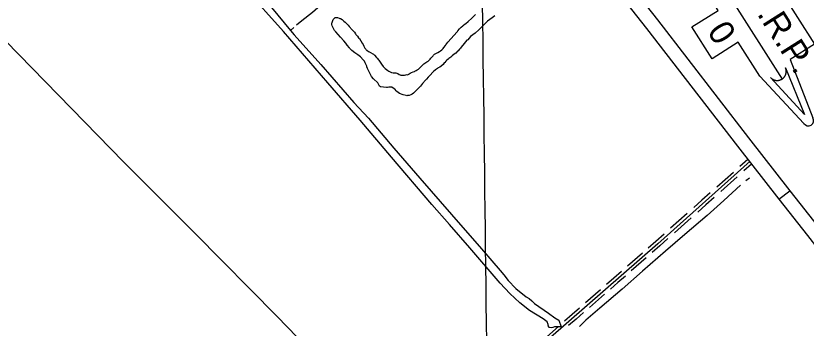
# Model space of a CAD drawing. Extents: x 3702978 to 3741108, y 397120 to 422907.
# Drawn here: x 3712602 to 3716580, y 417744 to 419319 of the extents above; entities that cross this region are included whole.
import ezdxf

# ---------------------------------------------------------------- set-up
doc = ezdxf.new("R2010")
doc.units = 0
for name, color, linetype in [('V-GRID-MAJR', 7, 'Continuous'), ('V-ROAD-CNTR', 7, 'Continuous'), ('V-SITE-VEGE', 7, 'Continuous'), ('V-TOPO-SHOR', 7, 'Continuous'), ('V-TOPO-WATR-IDEN', 7, 'Continuous')]:
    doc.layers.add(name, color=color, linetype=linetype)

msp = doc.modelspace()

# ---------------------------------------------------------------- linework, layer by layer
at = {"layer": 'V-GRID-MAJR'}
msp.add_spline([(3715151.476, 402623.691), (3715079.223, 408681.465), (3715006.939, 414741.843), (3714934.655, 420802.224), (3714934.624, 420804.822)], degree=3, dxfattribs=at)
at = {"layer": 'V-ROAD-CNTR'}
for points in [[(3714437.972, 420803.256), (3714574.337, 420608.545), (3714632.888, 420530.918), (3714682.486, 420466.822), (3714774.706, 420355.931), (3715157.03, 419961.431), (3715290.36, 419827.954), (3715412.039, 419698.216), (3715518.204, 419583.57), (3715775.96, 419254.704), (3716234.559, 418661.29), (3716442.007, 418393.909), (3716585.793, 418210.792), (3716689.926, 418077.31), (3716778.929, 417974.731), (3716867.49, 417879.826), (3716994.236, 417765.208), (3717139.264, 417654.689), (3717417.514, 417482.688), (3717810.191, 417252.227), (3718294.272, 416969.301), (3718986.57, 416565.649), (3719677.821, 416162.816), (3719893.898, 416035.258)], [(3714515.651, 420804.182), (3714630.628, 420650.883), (3714688.859, 420573.679), (3714737.432, 420510.907), (3714827.149, 420403.027), (3715207.239, 420010.832), (3715340.976, 419876.947), (3715463.567, 419746.236), (3715571.853, 419629.301), (3715831.545, 419297.965), (3716290.25, 418704.413), (3716497.531, 418437.247), (3716641.259, 418254.203), (3716744.33, 418122.083), (3716831.295, 418021.854), (3716916.949, 417930.064), (3717039.283, 417819.436), (3717179.223, 417712.794), (3717453.862, 417543.025), (3717845.787, 417313.005), (3718329.782, 417030.13), (3719022.041, 416626.501), (3719713.035, 416223.817), (3719920.188, 416105.369)], [(3716298.122, 418585.3), (3715832.901, 418169.955), (3715201.035, 417616.941), (3714529.227, 417025.75), (3713933.808, 416500.999), (3713913.076, 416483.623)], [(3716286.184, 418594.751), (3716246.594, 418559.406)], [(3716304.618, 418570.99), (3716266.574, 418537.026)], [(3716213.365, 418529.737), (3716130.29, 418455.568)], [(3716233.344, 418507.359), (3716150.27, 418433.19)], [(3716097.06, 418425.901), (3716055.522, 418388.817)], [(3716442.007, 418393.909), (3716497.531, 418437.247)], [(3716055.522, 418388.817), (3716013.984, 418351.733)], [(3716117.04, 418403.521), (3716075.502, 418366.437)], [(3716075.502, 418366.437), (3716033.964, 418329.353)], [(3715980.754, 418322.064), (3715897.679, 418247.895)], [(3716000.734, 418299.686), (3715917.659, 418225.518)], [(3715864.449, 418218.229), (3715822.911, 418181.145)], [(3715823.022, 418181.242), (3715785.411, 418148.324)], [(3715884.429, 418195.849), (3715842.891, 418158.765)], [(3715842.78, 418158.668), (3715805.169, 418125.75)], [(3715755.322, 418121.991), (3715680.1, 418056.156)], [(3715775.08, 418099.415), (3715699.858, 418033.58)], [(3715650.012, 418029.822), (3715612.4, 417996.905)], [(3715612.4, 417996.904), (3715574.789, 417963.986)], [(3715669.77, 418007.246), (3715632.158, 417974.329)], [(3715632.158, 417974.33), (3715594.547, 417941.412)], [(3715544.7, 417937.652), (3715469.478, 417871.817)], [(3715564.458, 417915.078), (3715489.236, 417849.243)], [(3715439.389, 417845.483), (3715401.778, 417812.565)], [(3715459.147, 417822.909), (3715421.536, 417789.991)], [(3715401.778, 417812.566), (3715364.166, 417779.649)], [(3715421.536, 417789.99), (3715383.924, 417757.073)], [(3715334.078, 417753.315), (3715258.855, 417687.481)]]:
    msp.add_lwpolyline(points, dxfattribs=at)
at = {"layer": 'V-SITE-VEGE'}
for points in [[(3714253.027, 419192.391), (3714236.168, 419211.459), (3714212.442, 419237.905), (3714206.197, 419245.288), (3714202.437, 419251.453), (3714194.263, 419268.107), (3714192.353, 419275.523), (3714192.924, 419281.718), (3714194.141, 419284.823), (3714198.359, 419300.33), (3714210.052, 419309.706), (3714215.002, 419310.364), (3714221.815, 419309.794), (3714229.268, 419306.755), (3714232.995, 419304.926), (3714235.477, 419304.324), (3714244.181, 419299.435), (3714253.529, 419291.456), (3714259.75, 419287.17), (3714270.353, 419276.721), (3714274.105, 419271.798), (3714279.722, 419265.647), (3714295.338, 419247.193), (3714305.951, 419235.505), (3714311.577, 419228.118), (3714314.084, 419224.421), (3714320.957, 419215.805), (3714326.585, 419208.416), (3714330.951, 419204.115), (3714338.461, 419193.027), (3714345.365, 419180.696), (3714349.754, 419173.299), (3714353.526, 419165.898), (3714359.168, 419156.032), (3714362.924, 419150.488), (3714366.044, 419147.416), (3714369.152, 419145.581), (3714376.628, 419139.446), (3714381.604, 419136.388), (3714384.084, 419135.788), (3714402.117, 419125.396), (3714406.483, 419121.094), (3714417.104, 419108.173), (3714422.714, 419103.26), (3714426.464, 419098.334), (3714428.96, 419095.876), (3714435.229, 419085.399), (3714442.737, 419074.93), (3714450.868, 419063.846), (3714460.233, 419053.391), (3714473.936, 419042.348), (3714479.531, 419039.292), (3714493.198, 419033.204), (3714501.257, 419032.026), (3714511.165, 419031.479), (3714514.882, 419030.887), (3714519.85, 419029.069), (3714524.198, 419027.244), (3714531.655, 419023.582), (3714536.007, 419021.139), (3714540.349, 419019.933), (3714543.456, 419018.718), (3714551.504, 419018.777), (3714558.922, 419020.072), (3714564.487, 419021.352), (3714567.573, 419022.611), (3714573.15, 419022.036), (3714577.475, 419022.685), (3714580.563, 419023.947), (3714582.402, 419026.437), (3714586.714, 419029.564), (3714594.115, 419033.335), (3714601.527, 419035.866), (3714608.322, 419037.775), (3714610.165, 419039.647), (3714617.573, 419042.796), (3714622.502, 419045.93), (3714628.046, 419049.686), (3714631.126, 419051.566), (3714647.105, 419067.782), (3714656.331, 419075.898), (3714671.112, 419086.536), (3714673.573, 419088.409), (3714676.651, 419090.91), (3714681.577, 419094.662), (3714687.106, 419100.276), (3714690.785, 419105.254), (3714701.836, 419117.72), (3714703.675, 419120.211), (3714706.747, 419123.33), (3714709.211, 419125.206), (3714715.377, 419128.345), (3714726.475, 419134.621), (3714735.105, 419139.636), (3714738.798, 419142.761), (3714746.189, 419147.769), (3714752.335, 419154.007), (3714756.632, 419158.992), (3714763.982, 419169.572), (3714767.054, 419172.689), (3714776.24, 419186.38)], [(3715012.999, 419319.397), (3714998.837, 419308.766), (3714976.677, 419291.268), (3714969.3, 419284.399), (3714941.034, 419255.711), (3714933.034, 419248.84), (3714913.353, 419231.356), (3714901.651, 419223.221), (3714890.575, 419213.854), (3714876.45, 419198.268), (3714872.762, 419195.145), (3714859.259, 419178.947), (3714843.912, 419161.498), (3714839.619, 419155.893), (3714834.708, 419150.286), (3714827.954, 419142.804), (3714824.88, 419139.685), (3714816.282, 419130.334), (3714808.27, 419125.323), (3714798.43, 419116.582), (3714791.661, 419110.96), (3714781.196, 419102.831), (3714778.12, 419100.333), (3714770.126, 419092.843), (3714767.048, 419090.345), (3714760.912, 419082.87), (3714758.447, 419081.612), (3714752.311, 419074.137), (3714743.089, 419065.4), (3714735.695, 419060.393), (3714728.3, 419056.004), (3714723.989, 419052.877), (3714714.748, 419046.616), (3714712.291, 419044.121), (3714705.516, 419039.116), (3714701.825, 419035.995), (3714685.239, 419018.536), (3714677.254, 419009.807), (3714668.664, 418999.217), (3714663.745, 418994.849), (3714648.401, 418976.777), (3714637.973, 418963.699), (3714630.608, 418954.976), (3714622.619, 418946.87), (3714602.938, 418929.386), (3714596.163, 418924.385), (3714589.382, 418920.619), (3714581.974, 418917.467), (3714573.932, 418916.787), (3714570.221, 418916.142), (3714566.498, 418917.352), (3714550.994, 418920.332), (3714533.617, 418926.394), (3714519.918, 418936.817), (3714515.552, 418941.119), (3714510.553, 418947.274), (3714509.297, 418949.739), (3714501.83, 418954.638), (3714494.369, 418958.914), (3714491.269, 418959.514), (3714488.174, 418959.49), (3714478.892, 418958.802), (3714473.328, 418957.522), (3714467.762, 418956.86), (3714438.012, 418960.973), (3714433.038, 418964.032), (3714429.919, 418967.104), (3714423.625, 418980.679), (3714402.42, 419001.57), (3714392.428, 419013.26), (3714388.041, 419020.037), (3714384.254, 419029.917), (3714382.368, 419033.615), (3714376.081, 419046.573), (3714372.317, 419053.354), (3714369.157, 419061.998), (3714367.895, 419065.085), (3714360.342, 419081.745), (3714356.567, 419089.765), (3714350.94, 419097.154), (3714337.21, 419111.91), (3714323.515, 419121.714), (3714313.557, 419128.452), (3714308.579, 419132.128), (3714293.02, 419143.159), (3714286.776, 419149.921), (3714283.03, 419154.228), (3714281.772, 419156.696), (3714269.904, 419170.848), (3714262.4, 419180.696), (3714253.027, 419192.391)], [(3714776.24, 419186.38), (3714822.913, 419237.496), (3714824.753, 419239.984), (3714827.206, 419243.099), (3714835.799, 419253.069), (3714838.871, 419256.188), (3714841.939, 419259.923), (3714843.785, 419261.795), (3714851.162, 419268.664), (3714855.473, 419271.789), (3714862.856, 419278.036), (3714867.171, 419280.545), (3714878.861, 419290.539), (3714897.309, 419307.392), (3714915.129, 419325.48)]]:
    msp.add_lwpolyline(points, dxfattribs=at)
at = {"layer": 'V-TOPO-SHOR'}
for p, q in [((3714000.74, 419259.704), (3713984.157, 419245.423)), ((3716293.908, 418500.113), (3716275.394, 418486.146))]:
    msp.add_line(p, q, dxfattribs=at)
for points in [[(3715284.613, 417747.293), (3715281.768, 417759.219), (3715280.82, 417762.887), (3715276.13, 417775.717), (3715256.711, 417792.116), (3715186.558, 417833.868), (3715138.49, 417872.108), (3715087.595, 417919.518), (3715039.428, 417970.623), (3714886.477, 418148.689), (3714784.509, 418267.397), (3714696.464, 418367.833), (3714492.522, 418606.171), (3714334.916, 418792.471), (3714172.7, 418980.576), (3713949.31, 419238.989), (3713755.629, 419457.187), (3713562.83, 419679.987), (3713350.455, 419940.318), (3713051.121, 420278.117), (3712833.302, 420529.218), (3712624.684, 420776.767)], [(3711374.968, 420388.136), (3711694.481, 420062.207), (3712077.813, 419673.57), (3712482.467, 419260.28), (3712881.573, 418851.542), (3713146.408, 418580.573), (3713502.863, 418222.982), (3713916.762, 417802.407), (3714266.804, 417442.01), (3714543.345, 417163.724)], [(3714598.94, 419815.402), (3714548.076, 419764.987), (3714491.68, 419704.12), (3714450.38, 419659.38), (3714401.13, 419606.971), (3714375.247, 419588.365), (3714350.962, 419570.173), (3714337.017, 419561.262), (3714324.287, 419550.758), (3714310.377, 419537.044), (3714274.604, 419502.351), (3714235.664, 419463.232), (3714200.301, 419427.341), (3714163.697, 419397.047), (3714135.867, 419371.22), (3714094.495, 419336.086), (3714041.569, 419293.66), (3714015.305, 419272.248)], [(3713856.212, 419400.957), (3713984.157, 419245.423), (3714002.73, 419222.844), (3714137.092, 419073.129), (3714303.922, 418882.301), (3714376.191, 418802.888), (3714504.132, 418651.286), (3714634.833, 418499.706), (3714795.161, 418318.019), (3714946.242, 418144.535), (3715039.87, 418034.953), (3715057.493, 418013.029), (3715080.677, 417984.714), (3715118.659, 417943.641), (3715170.432, 417901.751), (3715186.116, 417893.598), (3715199.061, 417882.666), (3715212.029, 417868.977), (3715282.229, 417820.794), (3715315.494, 417796.228), (3715334.873, 417785.345), (3715347.019, 417751.653)], [(3716249.487, 418464.677), (3716164.943, 418387.981), (3716081.989, 418312.361), (3715968.866, 418216.303), (3715872.137, 418133.134), (3715755.859, 418031.736), (3715654.404, 417940.553), (3715541.802, 417845.562), (3715471.509, 417784.399), (3715438.231, 417752.767)], [(3715347.019, 417751.653), (3715313.997, 417750.269), (3715304.82, 417748.362), (3715296.565, 417746.464), (3715289.206, 417747.328), (3715284.613, 417747.293)]]:
    msp.add_lwpolyline(points, dxfattribs=at)
at = {"layer": 'V-TOPO-WATR-IDEN'}
msp.add_line((3716056.264, 419634.49), (3716458.38, 418999.979), dxfattribs=at)
for points in [[(3715945.921, 419858.137), (3716157.438, 419637.764), (3716279.682, 419715.234), (3716621.485, 419175.888), (3716499.241, 419098.418), (3716613.512, 418804.716)], [(3716568.724, 418776.332), (3716346.24, 419014.011), (3716237.351, 419185.832), (3716106.149, 419102.684), (3716004.941, 419262.385), (3716136.143, 419345.533), (3716015.791, 419535.442), (3715901.133, 419829.753)]]:
    msp.add_lwpolyline(points, dxfattribs=at)
msp.add_lwpolyline([(3716476.316, 419055.742), (3716572.076, 418820.571), (3716400.295, 419007.566), (3716403.557, 419004.372), (3716406.993, 419001.614), (3716408.45, 419000.597), (3716409.763, 418999.749), (3716411.396, 418998.784), (3716413.007, 418997.915), (3716414.429, 418997.217), (3716416.414, 418996.342), (3716418.59, 418995.506), (3716419.823, 418995.089), (3716421.43, 418994.602), (3716423.574, 418994.049), (3716425.257, 418993.695), (3716427.082, 418993.381), (3716428.291, 418993.217), (3716429.624, 418993.071), (3716431.258, 418992.948), (3716432.764, 418992.886), (3716434.269, 418992.875), (3716435.501, 418992.901), (3716437.33, 418993.001), (3716439.077, 418993.167), (3716440.468, 418993.348), (3716442.097, 418993.614), (3716443.502, 418993.893), (3716444.741, 418994.177), (3716445.697, 418994.42), (3716447.148, 418994.835), (3716448.621, 418995.309), (3716450.001, 418995.802), (3716451.389, 418996.351), (3716452.657, 418996.899), (3716454.025, 418997.54), (3716455.13, 418998.102), (3716456.686, 418998.957), (3716458.38, 418999.979), (3716458.913, 419000.322), (3716459.682, 419000.836), (3716460.583, 419001.469), (3716461.443, 419002.099), (3716462.261, 419002.731), (3716463.045, 419003.365), (3716463.954, 419004.136), (3716464.575, 419004.688), (3716465.466, 419005.516), (3716466.277, 419006.31), (3716466.826, 419006.87), (3716468.195, 419008.353), (3716468.899, 419009.17), (3716469.371, 419009.742), (3716470.132, 419010.701), (3716470.788, 419011.573), (3716471.45, 419012.501), (3716472.203, 419013.621), (3716472.879, 419014.687), (3716473.384, 419015.529), (3716473.802, 419016.259), (3716474.348, 419017.264), (3716474.818, 419018.178), (3716475.335, 419019.252), (3716475.835, 419020.355), (3716476.306, 419021.483), (3716476.864, 419022.931), (3716477.233, 419023.98), (3716477.611, 419025.144), (3716477.949, 419026.3), (3716478.201, 419027.239), (3716478.453, 419028.267), (3716478.782, 419029.802), (3716478.793, 419029.86), (3716478.963, 419030.778), (3716479.075, 419031.458), (3716479.225, 419032.482), (3716479.381, 419033.758), (3716479.478, 419034.777), (3716479.546, 419035.695), (3716479.607, 419036.874), (3716479.635, 419038.011), (3716479.639, 419038.823), (3716479.623, 419039.883), (3716479.559, 419041.346), (3716479.498, 419042.209), (3716479.439, 419042.888), (3716479.378, 419043.509), (3716479.292, 419044.25), (3716479.161, 419045.221), (3716479.009, 419046.19), (3716478.839, 419047.147), (3716478.651, 419048.092), (3716478.374, 419049.307), (3716478.194, 419050.031), (3716477.881, 419051.184), (3716477.481, 419052.51), (3716477.156, 419053.491), (3716476.896, 419054.227), (3716476.643, 419054.908), (3716476.453, 419055.399)], close=True, dxfattribs=at)
msp.add_arc((3716591.118, 418790.524), 26.512, 212.363908, 32.363908, dxfattribs=at)

# ---------------------------------------------------------------- texts
for s, height, rotation, p in [('L.W.R.P.', 124.4995, 302.363844, (3716171.708, 419578.428)), ('0', 124.5, 302.363948, (3716078.522, 419240.69))]:
    msp.add_text(s, height=height, rotation=rotation, dxfattribs=at).set_placement(p)

doc.saveas('drawing.dxf')
